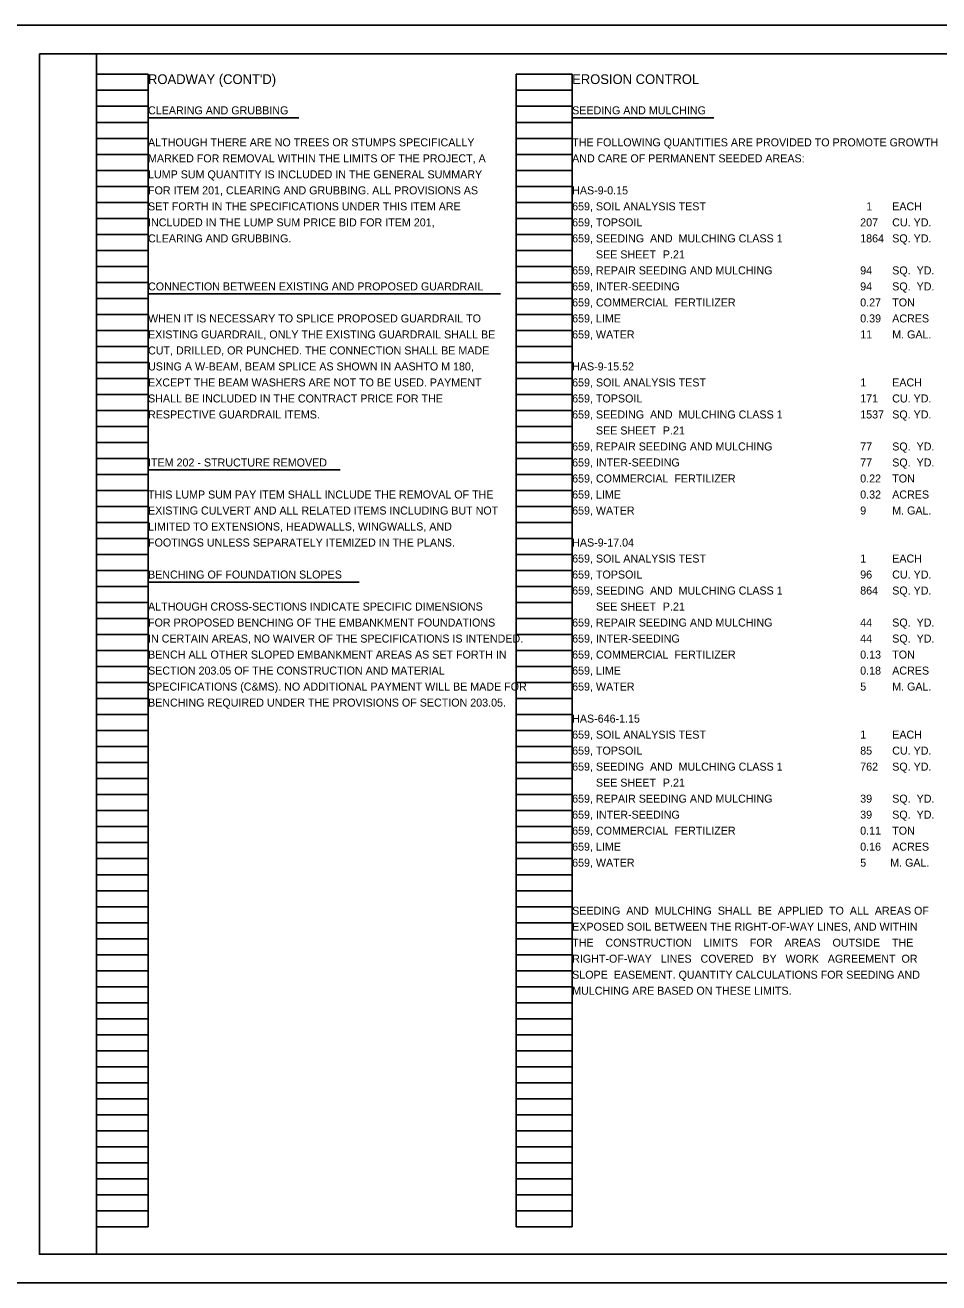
# Model space of a CAD drawing. Extents: x 0 to 102, y 0 to 22.
# Drawn here: x 34.25 to 50.24, y 0 to 22 of the extents above; entities that cross this region are included whole.
import ezdxf

# ---------------------------------------------------------------- set-up
doc = ezdxf.new("R2010")
doc.units = 0
doc.layers.add('SC_Scratch1', color=7, linetype='Continuous')
doc.layers.add('SH_Text', color=7, linetype='Continuous')

msp = doc.modelspace()

# ---------------------------------------------------------------- linework, layer by layer
at = {"layer": 'SC_Scratch1'}
for p, q in [((35.5, 0.98), (35.5, 21.14)), ((35.5, 21.14), (36.4, 21.14)), ((36.4, 0.98), (36.4, 21.14)), ((42.84, 0.98), (42.84, 21.14)), ((42.84, 21.14), (43.82, 21.14)), ((43.82, 0.98), (43.82, 21.14)), ((35.5, 20.86), (36.4, 20.86)), ((42.84, 20.86), (43.82, 20.86)), ((35.5, 20.58), (36.4, 20.58)), ((42.84, 20.58), (43.82, 20.58)), ((35.5, 20.3), (36.4, 20.3)), ((42.84, 20.3), (43.82, 20.3)), ((35.5, 20.02), (36.4, 20.02)), ((42.84, 20.02), (43.82, 20.02)), ((35.5, 19.74), (36.4, 19.74)), ((42.84, 19.74), (43.82, 19.74)), ((35.5, 19.46), (36.4, 19.46)), ((42.84, 19.46), (43.82, 19.46)), ((35.5, 19.18), (36.4, 19.18)), ((42.84, 19.18), (43.82, 19.18)), ((35.5, 18.9), (36.4, 18.9)), ((42.84, 18.9), (43.82, 18.9)), ((35.5, 18.62), (36.4, 18.62)), ((42.84, 18.62), (43.82, 18.62)), ((35.5, 18.34), (36.4, 18.34)), ((42.84, 18.34), (43.82, 18.34)), ((35.5, 18.06), (36.4, 18.06)), ((42.84, 18.06), (43.82, 18.06)), ((35.5, 17.78), (36.4, 17.78)), ((42.84, 17.78), (43.82, 17.78)), ((35.5, 17.5), (36.4, 17.5)), ((42.84, 17.5), (43.82, 17.5)), ((35.5, 17.22), (36.4, 17.22)), ((42.84, 17.22), (43.82, 17.22)), ((35.5, 16.94), (36.4, 16.94)), ((42.84, 16.94), (43.82, 16.94)), ((35.5, 16.66), (36.4, 16.66)), ((42.84, 16.66), (43.82, 16.66)), ((35.5, 16.38), (36.4, 16.38)), ((42.84, 16.38), (43.82, 16.38)), ((35.5, 16.1), (36.4, 16.1)), ((42.84, 16.1), (43.82, 16.1)), ((35.5, 15.82), (36.4, 15.82)), ((42.84, 15.82), (43.82, 15.82)), ((35.5, 15.54), (36.4, 15.54)), ((42.84, 15.54), (43.82, 15.54)), ((35.5, 15.26), (36.4, 15.26)), ((42.84, 15.26), (43.82, 15.26)), ((35.5, 14.98), (36.4, 14.98)), ((42.84, 14.98), (43.82, 14.98)), ((35.5, 14.7), (36.4, 14.7)), ((42.84, 14.7), (43.82, 14.7)), ((35.5, 14.42), (36.4, 14.42)), ((42.84, 14.42), (43.82, 14.42)), ((35.5, 14.14), (36.4, 14.14)), ((42.84, 14.14), (43.82, 14.14)), ((35.5, 13.86), (36.4, 13.86)), ((42.84, 13.86), (43.82, 13.86)), ((35.5, 13.58), (36.4, 13.58)), ((42.84, 13.58), (43.82, 13.58)), ((35.5, 13.3), (36.4, 13.3)), ((42.84, 13.3), (43.82, 13.3)), ((35.5, 13.02), (36.4, 13.02)), ((42.84, 13.02), (43.82, 13.02)), ((35.5, 12.74), (36.4, 12.74)), ((42.84, 12.74), (43.82, 12.74)), ((35.5, 12.46), (36.4, 12.46)), ((42.84, 12.46), (43.82, 12.46)), ((35.5, 12.18), (36.4, 12.18)), ((42.84, 12.18), (43.82, 12.18)), ((35.5, 11.9), (36.4, 11.9)), ((42.84, 11.9), (43.82, 11.9)), ((35.5, 11.62), (36.4, 11.62)), ((42.84, 11.62), (43.82, 11.62)), ((35.5, 11.34), (36.4, 11.34)), ((42.84, 11.34), (43.82, 11.34)), ((35.5, 11.06), (36.4, 11.06)), ((42.84, 11.06), (43.82, 11.06)), ((35.5, 10.78), (36.4, 10.78)), ((42.84, 10.78), (43.82, 10.78)), ((35.5, 10.5), (36.4, 10.5)), ((42.84, 10.5), (43.82, 10.5)), ((35.5, 10.22), (36.4, 10.22)), ((42.84, 10.22), (43.82, 10.22)), ((35.5, 9.94), (36.4, 9.94)), ((42.84, 9.94), (43.82, 9.94)), ((35.5, 9.66), (36.4, 9.66)), ((42.84, 9.66), (43.82, 9.66)), ((35.5, 9.38), (36.4, 9.38)), ((42.84, 9.38), (43.82, 9.38)), ((35.5, 9.1), (36.4, 9.1)), ((42.84, 9.1), (43.82, 9.1)), ((35.5, 8.82), (36.4, 8.82)), ((42.84, 8.82), (43.82, 8.82)), ((35.5, 8.54), (36.4, 8.54)), ((42.84, 8.54), (43.82, 8.54)), ((35.5, 8.26), (36.4, 8.26)), ((42.84, 8.26), (43.82, 8.26)), ((35.5, 7.98), (36.4, 7.98)), ((42.84, 7.98), (43.82, 7.98)), ((35.5, 7.7), (36.4, 7.7)), ((42.84, 7.7), (43.82, 7.7)), ((35.5, 7.42), (36.4, 7.42)), ((42.84, 7.42), (43.82, 7.42)), ((35.5, 7.14), (36.4, 7.14)), ((42.84, 7.14), (43.82, 7.14)), ((35.5, 6.86), (36.4, 6.86)), ((42.84, 6.86), (43.82, 6.86)), ((35.5, 6.58), (36.4, 6.58)), ((42.84, 6.58), (43.82, 6.58)), ((35.5, 6.3), (36.4, 6.3)), ((42.84, 6.3), (43.82, 6.3)), ((35.5, 6.02), (36.4, 6.02)), ((42.84, 6.02), (43.82, 6.02)), ((35.5, 5.74), (36.4, 5.74)), ((42.84, 5.74), (43.82, 5.74)), ((35.5, 5.46), (36.4, 5.46)), ((42.84, 5.46), (43.82, 5.46)), ((35.5, 5.18), (36.4, 5.18)), ((42.84, 5.18), (43.82, 5.18)), ((35.5, 4.9), (36.4, 4.9)), ((42.84, 4.9), (43.82, 4.9)), ((35.5, 4.62), (36.4, 4.62)), ((42.84, 4.62), (43.82, 4.62)), ((35.5, 4.34), (36.4, 4.34)), ((42.84, 4.34), (43.82, 4.34)), ((35.5, 4.06), (36.4, 4.06)), ((42.84, 4.06), (43.82, 4.06)), ((35.5, 3.78), (36.4, 3.78)), ((42.84, 3.78), (43.82, 3.78)), ((35.5, 3.5), (36.4, 3.5)), ((42.84, 3.5), (43.82, 3.5)), ((35.5, 3.22), (36.4, 3.22)), ((42.84, 3.22), (43.82, 3.22)), ((35.5, 2.94), (36.4, 2.94)), ((42.84, 2.94), (43.82, 2.94)), ((35.5, 2.66), (36.4, 2.66)), ((42.84, 2.66), (43.82, 2.66)), ((35.5, 2.38), (36.4, 2.38)), ((42.84, 2.38), (43.82, 2.38)), ((35.5, 2.1), (36.4, 2.1)), ((42.84, 2.1), (43.82, 2.1)), ((35.5, 1.82), (36.4, 1.82)), ((42.84, 1.82), (43.82, 1.82)), ((35.5, 1.54), (36.4, 1.54)), ((42.84, 1.54), (43.82, 1.54)), ((35.5, 1.26), (36.4, 1.26)), ((42.84, 1.26), (43.82, 1.26)), ((35.5, 0.98), (36.4, 0.98)), ((42.84, 0.98), (43.82, 0.98))]:
    msp.add_line(p, q, dxfattribs=at)
for points in [[(34, 22), (68, 22), (68, 0), (34, 0)], [(34.5, 21.5), (67.5, 21.5), (67.5, 0.5), (34.5, 0.5)], [(35.5, 21.5), (66, 21.5), (66, 0.5), (35.5, 0.5)]]:
    msp.add_lwpolyline(points, close=True, dxfattribs=at)
at = {"layer": 'SH_Text'}
for p, q in [((36.4, 20.379), (39.037, 20.379)), ((43.82, 20.379), (46.298, 20.379)), ((36.4, 17.299), (42.567, 17.299)), ((36.4, 14.219), (39.763, 14.219)), ((36.4, 12.259), (40.092, 12.259))]:
    msp.add_line(p, q, dxfattribs=at)

# ---------------------------------------------------------------- texts
for s, height, p in [("ROADWAY (CONT'D)", 0.17, (36.4, 20.97)), ('EROSION CONTROL', 0.17, (43.82, 20.97)), ('CLEARING AND GRUBBING', 0.14, (36.4, 20.44)), ('SEEDING AND MULCHING', 0.14, (43.82, 20.44)), ('ALTHOUGH THERE ARE NO TREES OR STUMPS SPECIFICALLY', 0.14, (36.4, 19.88)), ('THE FOLLOWING QUANTITIES ARE PROVIDED TO PROMOTE GROWTH', 0.14, (43.82, 19.88)), ('MARKED FOR REMOVAL WITHIN THE LIMITS OF THE PROJECT, A', 0.14, (36.4, 19.6)), ('AND CARE OF PERMANENT SEEDED AREAS:', 0.14, (43.82, 19.6)), ('LUMP SUM QUANTITY IS INCLUDED IN THE GENERAL SUMMARY', 0.14, (36.4, 19.32)), ('FOR ITEM 201, CLEARING AND GRUBBING. ALL PROVISIONS AS', 0.14, (36.4, 19.04)), ('HAS-9-0.15', 0.14, (43.82, 19.04)), ('SET FORTH IN THE SPECIFICATIONS UNDER THIS ITEM ARE', 0.14, (36.4, 18.76)), ('659, SOIL ANALYSIS TEST', 0.14, (43.82, 18.76)), ('  1', 0.14, (48.86, 18.76)), ('EACH', 0.14, (49.42, 18.76)), ('INCLUDED IN THE LUMP SUM PRICE BID FOR ITEM 201,', 0.14, (36.4, 18.48)), ('659, TOPSOIL', 0.14, (43.82, 18.48)), ('207', 0.14, (48.86, 18.48)), ('CU. YD.', 0.14, (49.42, 18.48)), ('CLEARING AND GRUBBING.', 0.14, (36.4, 18.2)), ('659, SEEDING  AND  MULCHING CLASS 1', 0.14, (43.82, 18.2)), ('1864', 0.14, (48.86, 18.2)), ('SQ. YD.', 0.14, (49.42, 18.2)), ('        SEE SHEET ', 0.14, (43.82, 17.92)), ('P.21', 0.14, (45.407, 17.92)), ('659, REPAIR SEEDING AND MULCHING', 0.14, (43.82, 17.64)), ('94', 0.14, (48.86, 17.64)), ('SQ.  YD.  ', 0.14, (49.42, 17.64)), ('CONNECTION BETWEEN EXISTING AND PROPOSED GUARDRAIL', 0.14, (36.4, 17.36)), ('659, INTER-SEEDING', 0.14, (43.82, 17.36)), ('94', 0.14, (48.86, 17.36)), ('SQ.  YD.', 0.14, (49.42, 17.36)), ('659, COMMERCIAL  FERTILIZER', 0.14, (43.82, 17.08)), ('0.27', 0.14, (48.86, 17.08)), ('TON', 0.14, (49.42, 17.08)), ('WHEN IT IS NECESSARY TO SPLICE PROPOSED GUARDRAIL TO', 0.14, (36.4, 16.8)), ('659, LIME', 0.14, (43.82, 16.8)), ('0.39', 0.14, (48.86, 16.8)), ('ACRES', 0.14, (49.42, 16.8)), ('EXISTING GUARDRAIL, ONLY THE EXISTING GUARDRAIL SHALL BE', 0.14, (36.4, 16.52)), ('659, WATER', 0.14, (43.82, 16.52)), ('11', 0.14, (48.86, 16.52)), ('M. GAL.', 0.14, (49.42, 16.52)), ('CUT, DRILLED, OR PUNCHED. THE CONNECTION SHALL BE MADE', 0.14, (36.4, 16.24)), ('USING A W-BEAM, BEAM SPLICE AS SHOWN IN AASHTO M 180,', 0.14, (36.4, 15.96)), ('HAS-9-15.52', 0.14, (43.82, 15.96)), ('EXCEPT THE BEAM WASHERS ARE NOT TO BE USED. PAYMENT', 0.14, (36.4, 15.68)), ('659, SOIL ANALYSIS TEST', 0.14, (43.82, 15.68)), ('1', 0.14, (48.86, 15.68)), ('EACH', 0.14, (49.42, 15.68)), ('SHALL BE INCLUDED IN THE CONTRACT PRICE FOR THE', 0.14, (36.4, 15.4)), ('659, TOPSOIL', 0.14, (43.82, 15.4)), ('171', 0.14, (48.86, 15.4)), ('CU. YD.', 0.14, (49.42, 15.4)), ('RESPECTIVE GUARDRAIL ITEMS.', 0.14, (36.4, 15.12)), ('659, SEEDING  AND  MULCHING CLASS 1', 0.14, (43.82, 15.12)), ('1537', 0.14, (48.86, 15.12)), ('SQ. YD.', 0.14, (49.42, 15.12)), ('        SEE SHEET ', 0.14, (43.82, 14.84)), ('P.21', 0.14, (45.407, 14.84)), ('659, REPAIR SEEDING AND MULCHING', 0.14, (43.82, 14.56)), ('77', 0.14, (48.86, 14.56)), ('SQ.  YD.  ', 0.14, (49.42, 14.56)), ('ITEM 202 - STRUCTURE REMOVED', 0.14, (36.4, 14.28)), ('659, INTER-SEEDING', 0.14, (43.82, 14.28)), ('77', 0.14, (48.86, 14.28)), ('SQ.  YD.', 0.14, (49.42, 14.28)), ('659, COMMERCIAL  FERTILIZER', 0.14, (43.82, 14)), ('0.22', 0.14, (48.86, 14)), ('TON', 0.14, (49.42, 14)), ('THIS LUMP SUM PAY ITEM SHALL INCLUDE THE REMOVAL OF THE ', 0.14, (36.4, 13.72)), ('659, LIME', 0.14, (43.82, 13.72)), ('0.32', 0.14, (48.86, 13.72)), ('ACRES', 0.14, (49.42, 13.72)), ('EXISTING CULVERT AND ALL RELATED ITEMS INCLUDING BUT NOT ', 0.14, (36.4, 13.44)), ('659, WATER', 0.14, (43.82, 13.44)), ('9', 0.14, (48.86, 13.44)), ('M. GAL.', 0.14, (49.42, 13.44)), ('LIMITED TO EXTENSIONS, HEADWALLS, WINGWALLS, AND ', 0.14, (36.4, 13.16)), ('FOOTINGS UNLESS SEPARATELY ITEMIZED IN THE PLANS.', 0.14, (36.4, 12.88)), ('HAS-9-17.04', 0.14, (43.82, 12.88)), ('659, SOIL ANALYSIS TEST', 0.14, (43.82, 12.6)), ('1', 0.14, (48.86, 12.6)), ('EACH', 0.14, (49.42, 12.6)), ('BENCHING OF FOUNDATION SLOPES', 0.14, (36.4, 12.32)), ('659, TOPSOIL', 0.14, (43.82, 12.32)), ('96', 0.14, (48.86, 12.32)), ('CU. YD.', 0.14, (49.42, 12.32)), ('659, SEEDING  AND  MULCHING CLASS 1', 0.14, (43.82, 12.04)), ('864', 0.14, (48.86, 12.04)), ('SQ. YD.', 0.14, (49.42, 12.04)), ('ALTHOUGH CROSS-SECTIONS INDICATE SPECIFIC DIMENSIONS ', 0.14, (36.4, 11.76)), ('        SEE SHEET ', 0.14, (43.82, 11.76)), ('P.21', 0.14, (45.407, 11.76)), ('FOR PROPOSED BENCHING OF THE EMBANKMENT FOUNDATIONS ', 0.14, (36.4, 11.48)), ('659, REPAIR SEEDING AND MULCHING', 0.14, (43.82, 11.48)), ('44', 0.14, (48.86, 11.48)), ('SQ.  YD.  ', 0.14, (49.42, 11.48)), ('IN CERTAIN AREAS, NO WAIVER OF THE SPECIFICATIONS IS INTENDED. ', 0.14, (36.4, 11.2)), ('659, INTER-SEEDING', 0.14, (43.82, 11.2)), ('44', 0.14, (48.86, 11.2)), ('SQ.  YD.', 0.14, (49.42, 11.2)), ('BENCH ALL OTHER SLOPED EMBANKMENT AREAS AS SET FORTH IN ', 0.14, (36.4, 10.92)), ('659, COMMERCIAL  FERTILIZER', 0.14, (43.82, 10.92)), ('0.13', 0.14, (48.86, 10.92)), ('TON', 0.14, (49.42, 10.92)), ('SECTION 203.05 OF THE CONSTRUCTION AND MATERIAL ', 0.14, (36.4, 10.64)), ('659, LIME', 0.14, (43.82, 10.64)), ('0.18', 0.14, (48.86, 10.64)), ('ACRES', 0.14, (49.42, 10.64)), ('SPECIFICATIONS (C&MS). NO ADDITIONAL PAYMENT WILL BE MADE FOR ', 0.14, (36.4, 10.36)), ('659, WATER', 0.14, (43.82, 10.36)), ('5', 0.14, (48.86, 10.36)), ('M. GAL.', 0.14, (49.42, 10.36)), ('BENCHING REQUIRED UNDER THE PROVISIONS OF SECTION 203.05.', 0.14, (36.4, 10.08)), ('HAS-646-1.15', 0.14, (43.82, 9.8)), ('659, SOIL ANALYSIS TEST', 0.14, (43.82, 9.52)), ('1', 0.14, (48.86, 9.52)), ('EACH', 0.14, (49.42, 9.52)), ('659, TOPSOIL', 0.14, (43.82, 9.24)), ('85', 0.14, (48.86, 9.24)), ('CU. YD.', 0.14, (49.42, 9.24)), ('659, SEEDING  AND  MULCHING CLASS 1', 0.14, (43.82, 8.96)), ('762', 0.14, (48.86, 8.96)), ('SQ. YD.', 0.14, (49.42, 8.96)), ('        SEE SHEET ', 0.14, (43.82, 8.68)), ('P.21', 0.14, (45.407, 8.68)), ('659, REPAIR SEEDING AND MULCHING', 0.14, (43.82, 8.4)), ('39', 0.14, (48.86, 8.4)), ('SQ.  YD.  ', 0.14, (49.42, 8.4)), ('659, INTER-SEEDING', 0.14, (43.82, 8.12)), ('39', 0.14, (48.86, 8.12)), ('SQ.  YD.', 0.14, (49.42, 8.12)), ('659, COMMERCIAL  FERTILIZER', 0.14, (43.82, 7.84)), ('0.11', 0.14, (48.86, 7.84)), ('TON', 0.14, (49.42, 7.84)), ('659, LIME', 0.14, (43.82, 7.56)), ('0.16', 0.14, (48.86, 7.56)), ('ACRES', 0.14, (49.42, 7.56)), ('659, WATER', 0.14, (43.82, 7.28)), ('5', 0.14, (48.86, 7.28)), ('        M. GAL.', 0.14, (48.969, 7.28)), ('SEEDING  AND  MULCHING  SHALL  BE  APPLIED  TO  ALL  AREAS OF', 0.14, (43.82, 6.44)), ('EXPOSED SOIL BETWEEN THE RIGHT-OF-WAY LINES, AND WITHIN', 0.14, (43.82, 6.16)), ('THE    CONSTRUCTION    LIMITS    FOR    AREAS    OUTSIDE    THE', 0.14, (43.82, 5.88)), ('RIGHT-OF-WAY   LINES   COVERED   BY   WORK   AGREEMENT  OR ', 0.14, (43.82, 5.6)), ('SLOPE  EASEMENT. QUANTITY CALCULATIONS FOR SEEDING AND', 0.14, (43.82, 5.32)), ('MULCHING ARE BASED ON THESE LIMITS.', 0.14, (43.82, 5.04))]:
    msp.add_text(s, height=height, dxfattribs=at).set_placement(p)

doc.saveas('drawing.dxf')
